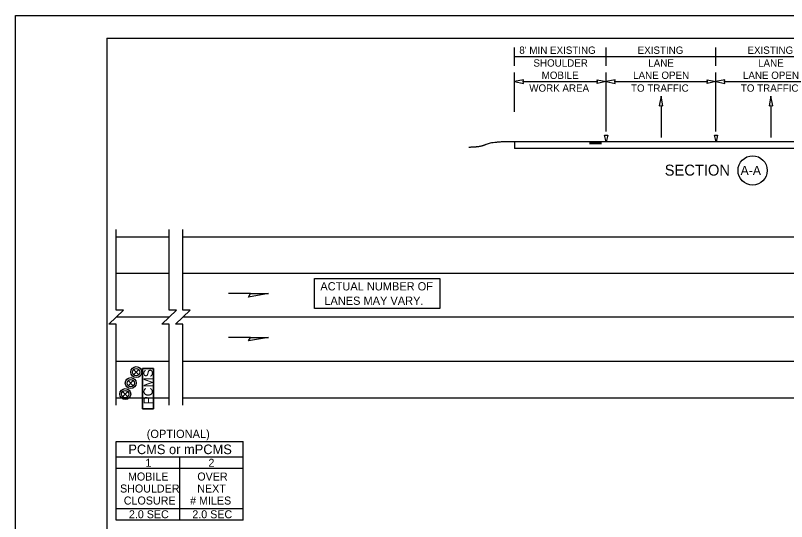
# Model space of a CAD drawing. Extents: x 0 to 17, y 0 to 11.
# Drawn here: x 0 to 8.43, y 5.47 to 11 of the extents above; entities that cross this region are included whole.
import ezdxf

# ---------------------------------------------------------------- set-up
doc = ezdxf.new("R2010")
doc.units = 0
for name, color, linetype in [('RD_ED_ShoulderPavedEdge', 7, 'Continuous'), ('RD_MK_LineEdgeWhite', 7, 'Continuous'), ('RD_MK_LineEdgeYellow', 7, 'Continuous'), ('RD_MK_LineLane', 7, 'Continuous'), ('SH_GI_PlotLimits', 7, 'Continuous'), ('SH_GI_SheetBorder3', 7, 'Continuous'), ('SH_TI_Tables', 7, 'Continuous'), ('SH_TI_WZSectionCut', 7, 'Continuous'), ('TR_WZ_ArrowLeftStrRightTurn', 7, 'Continuous'), ('TR_WZ_PCMS', 7, 'Continuous'), ('TR_WZ_PortableChangeMessageSign', 7, 'Continuous'), ('TR_WZ_TrafficSafetyDrum', 7, 'Continuous'), ('TR_WZ_WorkZoneDetails', 7, 'Continuous')]:
    doc.layers.add(name, color=color, linetype=linetype)

msp = doc.modelspace()

# ---------------------------------------------------------------- linework, layer by layer
at = {"layer": 'RD_ED_ShoulderPavedEdge'}
for p, q in [((1.1016, 8.5807), (1.6783, 8.5807)), ((1.8283, 8.5807), (16.62, 8.5807)), ((1.1016, 6.8207), (1.6783, 6.8207)), ((1.8283, 6.8207), (16.62, 6.8207))]:
    msp.add_line(p, q, dxfattribs=at)
at = {"layer": 'RD_MK_LineEdgeWhite'}
for p, q in [((1.1016, 7.2207), (1.6783, 7.2207)), ((1.8283, 7.2207), (16.62, 7.2207))]:
    msp.add_line(p, q, dxfattribs=at)
at = {"layer": 'RD_MK_LineEdgeYellow'}
for p, q in [((1.1016, 8.1807), (1.6783, 8.1807)), ((1.8283, 8.1807), (16.62, 8.1807))]:
    msp.add_line(p, q, dxfattribs=at)
at = {"layer": 'RD_MK_LineLane'}
for p, q in [((1.6783, 7.7007), (1.1016, 7.7007)), ((16.62, 7.7007), (1.8283, 7.7007))]:
    msp.add_line(p, q, dxfattribs=at)
at = {"layer": 'SH_GI_PlotLimits'}
msp.add_lwpolyline([(0, 11), (17, 11), (17, 0), (0, 0)], close=True, dxfattribs=at)
at = {"layer": 'SH_GI_SheetBorder3'}
for q in [(16.75, 10.75), (1, 0.25)]:
    msp.add_line((1, 10.75), q, dxfattribs=at)
at = {"layer": 'SH_TI_Tables'}
msp.add_lwpolyline([(3.266, 8.1232), (4.6358, 8.1232), (4.6358, 7.7968), (3.266, 7.7968)], close=True, dxfattribs=at)
at = {"layer": 'SH_TI_WZSectionCut'}
for p, q in [((5.4546, 10.45), (5.4546, 10.65)), ((6.4546, 10.45), (6.4546, 10.65)), ((7.6546, 10.45), (7.6546, 10.65)), ((5.4546, 10.55), (6.4546, 10.55)), ((6.4546, 10.55), (7.6546, 10.55)), ((7.6546, 10.55), (8.8546, 10.55)), ((5.4546, 9.9449), (5.4546, 10.376)), ((6.4546, 9.7297), (6.4546, 10.376)), ((7.6546, 9.7297), (7.6546, 10.376)), ((5.5484, 10.276), (6.3609, 10.276)), ((6.5484, 10.276), (7.5609, 10.276)), ((7.7484, 10.276), (8.7609, 10.276)), ((5.4546, 9.6199), (5.4546, 9.5449)), ((9.8546, 9.6199), (5.4546, 9.6199)), ((6.2716, 9.6147), (6.4046, 9.6147)), ((6.2716, 9.6091), (6.4046, 9.6091)), ((9.8546, 9.5449), (5.4546, 9.5449)), ((6.2716, 9.6034), (6.4046, 9.6034)), ((6.2716, 9.5982), (6.4046, 9.5982))]:
    msp.add_line(p, q, dxfattribs=at)
for points in [[(5.4546, 10.276), (5.5529, 10.2567), (5.5484, 10.276), (5.5529, 10.2953)], [(6.4546, 10.276), (6.3564, 10.2567), (6.3609, 10.276), (6.3564, 10.2953)], [(6.4546, 10.276), (6.5529, 10.2567), (6.5484, 10.276), (6.5529, 10.2953)], [(7.6546, 10.276), (7.5564, 10.2567), (7.5609, 10.276), (7.5564, 10.2953)], [(7.6546, 10.276), (7.7529, 10.2567), (7.7484, 10.276), (7.7529, 10.2953)], [(6.4379, 9.6897), (6.4713, 9.6897), (6.4546, 9.6199)], [(7.638, 9.6897), (7.6713, 9.6897), (7.6547, 9.6199)]]:
    msp.add_lwpolyline(points, close=True, dxfattribs=at)
msp.add_circle((8.055, 9.305), 0.16, dxfattribs=at)
msp.add_open_spline([(5.4546, 9.6199), (5.2035, 9.6199), (5.078, 9.5578), (4.9525, 9.5578)], degree=2, dxfattribs=at)
at = {"layer": 'TR_WZ_ArrowLeftStrRightTurn'}
for p, q in [((7.0546, 10.0168), (7.0546, 9.667)), ((8.2546, 10.0168), (8.2546, 9.667))]:
    msp.add_line(p, q, dxfattribs=at)
for points in [[(7.0546, 10.117), (7.034, 10.0119), (7.0546, 10.0168), (7.0752, 10.0119)], [(8.2546, 10.117), (8.234, 10.0119), (8.2546, 10.0168), (8.2752, 10.0119)]]:
    msp.add_lwpolyline(points, close=True, dxfattribs=at)
at = {"layer": 'TR_WZ_PCMS'}
for points in [[(1.39, 7.1407), (1.51, 7.1407), (1.51, 6.7007), (1.39, 6.7007), (1.39, 7.1407)], [(1.39, 6.7007), (1.51, 6.7007), (1.51, 7.1407), (1.39, 7.1407), (1.39, 6.7007)]]:
    msp.add_lwpolyline(points, dxfattribs=at)
at = {"layer": 'TR_WZ_PortableChangeMessageSign'}
for p, q in [((1.1016, 6.3407), (2.4876, 6.3407)), ((1.1016, 5.4839), (1.1016, 6.3407)), ((2.4876, 5.4839), (2.4876, 6.3407)), ((2.4876, 6.1727), (1.1016, 6.1727)), ((1.7946, 5.4839), (1.7946, 6.1727)), ((1.7946, 6.0467), (1.1016, 6.0467)), ((2.4876, 6.0467), (1.7946, 6.0467)), ((1.1016, 5.6099), (1.7946, 5.6099)), ((1.7946, 5.6099), (2.4876, 5.6099)), ((2.4876, 5.4839), (1.1016, 5.4839))]:
    msp.add_line(p, q, dxfattribs=at)
at = {"layer": 'TR_WZ_TrafficSafetyDrum'}
for p, q in [((1.2917, 7.129), (1.3483, 7.0724)), ((1.3483, 7.129), (1.2917, 7.0724)), ((1.2317, 7.009), (1.2883, 6.9524)), ((1.2883, 7.009), (1.2317, 6.9524)), ((1.1717, 6.889), (1.2283, 6.8324)), ((1.2283, 6.889), (1.1717, 6.8324))]:
    msp.add_line(p, q, dxfattribs=at)
for centre, radius in [((1.32, 7.1007), 0.06), ((1.32, 7.1007), 0.06), ((1.32, 7.1007), 0.04), ((1.26, 6.9807), 0.06), ((1.26, 6.9807), 0.06), ((1.26, 6.9807), 0.04), ((1.2, 6.8607), 0.06), ((1.2, 6.8607), 0.06), ((1.2, 6.8607), 0.04)]:
    msp.add_circle(centre, radius, dxfattribs=at)
at = {"layer": 'TR_WZ_WorkZoneDetails'}
for p, q in [((2.5694, 7.96), (2.3283, 7.96)), ((2.5694, 7.48), (2.3283, 7.48))]:
    msp.add_line(p, q, dxfattribs=at)
for points in [[(1.1016, 6.7407), (1.1016, 7.6233), (1.0216, 7.6233), (1.1817, 7.7782), (1.1016, 7.7782), (1.1016, 8.6607)], [(1.6783, 6.7407), (1.6783, 7.6233), (1.5983, 7.6233), (1.7583, 7.7782), (1.6783, 7.7782), (1.6783, 8.6607)], [(1.8283, 6.7407), (1.8283, 7.6233), (1.7483, 7.6233), (1.9083, 7.7782), (1.8283, 7.7782), (1.8283, 8.6607)]]:
    msp.add_lwpolyline(points, dxfattribs=at)
for points in [[(2.766, 7.96), (2.5471, 7.9214), (2.5694, 7.96)], [(2.766, 7.48), (2.5471, 7.4414), (2.5694, 7.48)]]:
    msp.add_lwpolyline(points, close=True, dxfattribs=at)

# ---------------------------------------------------------------- texts
at = {"layer": 'SH_TI_Tables'}
for s, p in [('ACTUAL NUMBER OF', (3.3317, 7.9938)), ('LANES MAY VARY.', (3.375, 7.8363))]:
    msp.add_text(s, height=0.09, rotation=360, dxfattribs=at).set_placement(p)
at = {"layer": 'SH_TI_WZSectionCut'}
for s, p in [("8' MIN EXISTING", (5.5057, 10.58)), ('SHOULDER', (5.6601, 10.44)), ('MOBILE', (5.7496, 10.306)), ('LANE OPEN', (6.7489, 10.306)), ('LANE OPEN', (7.9489, 10.306)), ('WORK AREA', (5.6142, 10.166)), ('TO TRAFFIC', (6.7261, 10.166)), ('TO TRAFFIC', (7.9261, 10.166))]:
    msp.add_text(s, height=0.08, dxfattribs=at).set_placement(p)
for s, height, p in [('EXISTING', 0.08, (6.7986, 10.58)), ('EXISTING', 0.08, (7.9986, 10.58)), ('LANE', 0.08, (6.9145, 10.44)), ('LANE', 0.08, (8.1145, 10.44)), ('SECTION', 0.12, (7.0943, 9.2489)), ('A-A', 0.1, (7.9231, 9.255))]:
    msp.add_text(s, height=height, rotation=360, dxfattribs=at).set_placement(p)
at = {"layer": 'TR_WZ_PCMS'}
msp.add_text('PCMS', height=0.1, rotation=90, dxfattribs=at).set_placement((1.5, 6.7471))
at = {"layer": 'TR_WZ_PortableChangeMessageSign'}
for s, height, p in [('PCMS or mPCMS', 0.105, (1.2335, 6.2042)), ('1', 0.0875, (1.4208, 6.066)), ('2', 0.0875, (2.1087, 6.066)), ('MOBILE', 0.0875, (1.2299, 5.9158)), ('OVER', 0.0875, (1.9874, 5.9158)), ('SHOULDER', 0.0875, (1.1431, 5.7846)), ('NEXT', 0.0875, (1.9866, 5.7846)), ('CLOSURE', 0.0875, (1.184, 5.6533)), ('# MILES', 0.0875, (1.9088, 5.6533)), ('2.0 SEC', 0.0875, (1.2399, 5.5032)), ('2.0 SEC', 0.0875, (1.9329, 5.5032))]:
    msp.add_text(s, height=height, rotation=360, dxfattribs=at).set_placement(p)
at = {"layer": 'TR_WZ_WorkZoneDetails'}
msp.add_text('(OPTIONAL)', height=0.09, dxfattribs=at).set_placement((1.4346, 6.3807))

doc.saveas('drawing.dxf')
